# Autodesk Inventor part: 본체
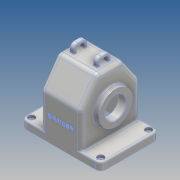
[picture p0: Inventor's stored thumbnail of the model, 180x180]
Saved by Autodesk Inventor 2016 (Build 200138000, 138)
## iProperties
Created: 2016-12
Part Number: 본체
Material: 알루미늄 6061
Document SubType Name: Modeling
Designer: Administrator
Density: 2.7 g/cm^3
Appearance: 알루미늄 - 평지
Mass: 1063.31 g
Surface Area: 1138.22 cm^2
Volume: 393.819 cm^3
Author: Administrator
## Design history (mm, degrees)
sketch "스케치1"
  geometry: L1 (-65, 55)-(65, 55); L2 (75, 45)-(75, -45); L3 (65, -55)-(-65, -55); L4 (-75, -45)-(-75, 45); L5 (-75, 55)-(75, -55); L6 (75, 55)-(-75, -55); A1 r 10 centre (-65, 45) between (-65, 55) and (-75, 45); A2 r 10 centre (-65, -45) between (-75, -45) and (-65, -55); A3 r 10 centre (65, -45) between (65, -55) and (75, -45); A4 r 10 centre (65, 45) between (75, 45) and (65, 55); 1 further point
  constraints: 12 end point, 8 point on circle, 8 point on line, 8 tangent, 4 centre point, 3 equal radius, 2 midpoint, 2 parallel, 1 horizontal, 1 perpendicular
  dimensions: "d0" = 150 distance of L5.end L6.end; "d1" = 110 distance of L6.start L5.end; "d2" = 10 radius of A1
extrude "돌출1" new body sketch "스케치1" distance "d3" = 15; taper "d4" = 0 deg
sketch "스케치2"
  geometry: L1 (-45, 15)-(-55, 15) reference; L2 (45, 15)-(-45, 15) reference; L3 (55, 15)-(45, 15) reference; L4 (-55, 15)-(-55, 76.847); L5 (-53.192, 82.583)-(-26.477, 120.736); L6 (-18.285, 125)-(18.285, 125); L7 (26.477, 120.736)-(53.192, 82.583); L8 (55, 76.847)-(55, 15); L9 (45, 0)-(-45, 0) reference; A1 r 10 centre (-18.285, 115) between (-18.285, 125) and (-26.477, 120.736); A2 r 10 centre (18.285, 115) between (26.477, 120.736) and (18.285, 125); A3 r 10 centre (45, 76.847) between (55, 76.847) and (53.192, 82.583); A4 r 10 centre (-45, 76.847) between (-53.192, 82.583) and (-55, 76.847); 3 further points
  constraints: 10 end point, 8 point on circle, 8 tangent, 4 centre point, 4 point on line, 3 equal radius, 2 vertical, 1 perpendicular
  dimensions: "d5" = 80 distance from line of point (55, 80) L9; "d6" = 80 distance from line of L9 point (-55, 80) (= d5); "d7" = 125 distance between parallel lines of L9 L6; "d8" = 35 deg angle of L5 L4; "d9" = 35 deg angle of L8 L7; "d10" = 10 radius of A1
extrude "돌출2" join sketch "스케치2" stored distance "d11" = 77; taper "d12" = 0 deg
sketch "스케치3"
  geometry: L1 (43.5, 65)-(-48.5, 65); L2 (-65, 0)-(65, 0) reference; L3 (38.5, 76.847)-(38.5, 15) reference; L4 (-38.5, 15)-(-38.5, 76.847) reference; L5 (43.5, 65)-(43.5, 102.5); L6 (43.5, 102.5)-(38.5, 102.5); L7 (38.5, 120.736)-(38.5, 82.583) reference; L8 (-38.5, 82.583)-(-38.5, 120.736) reference; L9 (-38.5, 96)-(-48.5, 96); L10 (-48.5, 96)-(-48.5, 65); L11 (-38.5, 96)-(38.5, 96); L12 (38.5, 102.5)-(38.5, 96); 1 further point
  constraints: 14 end point, 4 point on line, 3 perpendicular, 2 horizontal, 1 vertical
  dimensions: "d14" = 75 diameter of L6 L1; "d15" = 5 distance between parallel lines of L7 L5; "d17" = 65 distance between parallel lines of L2 L1; "d18" = 62 diameter of L9 L1; "d19" = 87 distance between parallel lines of L7 L10
revolve "회전1" sketch "스케치3" stored, may be unused: angle "d20" = 90 deg
sketch "스케치4"
  geometry: L1 (45, 0)-(-45, 0) reference; L2 (-53.192, 82.583)-(-26.477, 120.736) reference; L3 (-18.285, 125)-(18.285, 125) reference; L4 (26.477, 120.736)-(53.192, 82.583) reference; L5 (55, 76.847)-(55, 15) reference; L6 (-55, 15)-(-55, 76.847) reference; L7 (-55, 0)-(-55, 15) reference; L8 (55, 0)-(55, 15) reference; L9 (50, -5)-(50, 15); L10 (50, 15)-(50, 76.847); L11 (49.096, 79.715)-(22.381, 117.868); L12 (18.285, 120)-(-18.285, 120); L13 (-22.381, 117.868)-(-49.096, 79.715); L14 (-50, 76.847)-(-50, 15); L15 (-50, 15)-(-50, -5); L16 (-45, 0)-(-55, 0) reference; L17 (55, 0)-(45, 0) reference; L18 (-50, -5)-(50, -5); A1 r 10 centre (-18.285, 115) between (-18.285, 125) and (-26.477, 120.736) reference; A2 r 10 centre (18.285, 115) between (26.477, 120.736) and (18.285, 125) reference; A3 r 10 centre (45, 76.847) between (55, 76.847) and (53.192, 82.583) reference; A4 r 10 centre (-45, 76.847) between (-53.192, 82.583) and (-55, 76.847) reference; A5 r 5 centre (45, 76.847) between (50, 76.847) and (49.096, 79.715); A6 r 5 centre (18.285, 115) between (22.381, 117.868) and (18.285, 120); A7 r 5 centre (-18.285, 115) between (-18.285, 120) and (-22.381, 117.868); A8 r 5 centre (-45, 76.847) between (-49.096, 79.715) and (-50, 76.847); 1 further point
  constraints: 18 end point, 8 point on circle, 4 centre point, 2 collinear, 1 horizontal, 8 other
  dimensions: "d21" = 5 distance between parallel lines of L3 L12; "d22" = 5 distance between parallel lines of L1 L18
extrude "돌출3" cut sketch "스케치4" stored distance "d23" = 67; taper "d24" = 0 deg
fillet "모깎기1" dims "d25" = 8
fillet "모깎기2" dims "d26" = 3
sketch "스케치5"
  geometry: L1 (33.5, 106)-(19.5, 92); L2 (33.5, 65)-(-33.5, 65); L3 (-65, 0)-(65, 0) reference; L4 (33.5, 76.847)-(33.5, 0) reference; L5 (-33.5, 0)-(-33.5, 76.847) reference; L6 (43.5, 27.5)-(43.5, 102.5) reference; L7 (19.5, 65)-(19.5, 92); L8 (33.5, 116.147)-(33.5, 77.994) reference; L9 (33.5, 106)-(33.5, 65); 1 further point
  constraints: 9 end point, 4 point on line, 1 horizontal, 1 parallel
  dimensions: "d27" = 65 distance between parallel lines of L3 L2; "d28" = 24 distance between parallel lines of L6 L7; "d29" = 45 deg angle of L7 L1; "d30" = 27 distance of L7.start L1.end
revolve "회전2" sketch "스케치5" stored, may be unused: angle "d31" = 90 deg
sketch "스케치6"
  geometry: L1 (43.5, 27.5)-(43.5, 102.5) reference; L2 (43.5, 65)-(-48.5, 65); L3 (-48.5, 34)-(-48.5, 96) reference; L4 (43.5, 85)-(-48.5, 85); L5 (43.5, 85)-(43.5, 65); L6 (-48.5, 65)-(-48.5, 85); 1 further point
  constraints: 8 end point, 2 midpoint, 1 collinear, 1 parallel, 1 perpendicular
  dimensions: "d32" = 20 distance between parallel lines of L2 L4
revolve "회전3" sketch "스케치6" stored, may be unused: angle "d33" = 90 deg
fillet "모깎기3" dims "d34" = 3
sketch "스케치7"
  geometry: L1 (4.5, -5.785)-(12.5, -5.785); L2 (12.5, -5.785)-(12.5, -30.785); L3 (12.5, -30.785)-(4.5, -30.785); L4 (4.5, -30.785)-(4.5, -5.785); L5 (48.5, -5.785)-(56.5, -5.785); L6 (56.5, -5.785)-(56.5, -30.785); L7 (56.5, -30.785)-(48.5, -30.785); L8 (48.5, -30.785)-(48.5, -5.785); 2 further points
  constraints: 16 end point, 4 parallel, 2 horizontal, 2 perpendicular, 2 point on line, 1 horizontal alignment, 1 midpoint
  dimensions: "d35" = 25 distance of L3.end L1.start; "d36" = 8 distance of L1.start L1.end; "d37" = 8 distance of L5.start L5.end (= d36); "d38" = 18 distance from line of point (30.5, -18.285) L8; "d39" = 36 distance between parallel lines of L8 L2
extrude "돌출4" join sketch "스케치7" distance "d40" = 15; taper "d41" = 0 deg
sketch "스케치8"
  geometry: L1 (0, 25)-(0, 0) reference; L2 (-15, 0)-(-15, 25) reference; L3 (0, 0)-(-15, 0) reference; L4 (-10, 20)-(0, 20); L5 (0, 5)-(-10, 5); L6 (-10, 5)-(-10, 20); 1 further point
  constraints: 6 end point, 2 point on line, 1 other
  dimensions: "d42" = 5 distance between parallel lines of L2 L6; "d43" = 15 distance between parallel lines of L5 L4
extrude "돌출5" cut sketch "스케치8" stored distance "d44" = 15; taper "d45" = 0 deg
fillet "모깎기4" dims "d46" = 8
fillet "모깎기5" dims "d47" = 3
fillet "모깎기6" dims "d48" = 1
fillet "모깎기7" dims "d49" = 1
sketch "스케치9"
  geometry: A1 r 7 centre (65, -45) between (65, -52) and (72, -45) reference; A2 r 7 centre (65, 45) between (72, 45) and (65, 52) reference; A3 r 10 centre (-65, 45) between (-65, 55) and (-75, 45) reference; A4 r 10 centre (-65, -45) between (-75, -45) and (-65, -55) reference; 5 further points
  constraints: 4 coincident
hole "구멍1" sketch "스케치9" at (-65, 45), (-65, -45), (65, -45), (65, 45) diameter "d50" = 5; stored, may be unused: countersink angle "d54" = 90 deg, drill point angle "d56" = 0 deg; dims "d51" = 6, "d52" = 12, "d53" = 5, "d55" = 8
sketch "스케치10"
  geometry: C1 r 20 at (0, 0) reference; C2 r 31 at (0, 0) reference; A1 r 26 centre (0, 0) between (-26, 0) and (26, 0); 3 further points
  constraints: 4 point on circle, 2 horizontal alignment, 2 vertical alignment, 1 centre point, 1 coincident
  dimensions: "d57" = 52 diameter of A1
hole "구멍2" sketch "스케치10" at (-26, 0), (26, 0), (0, -26), (0, 26) diameter "d58" = 2.459; stored, may be unused: countersink angle "d62" = 90 deg, drill point angle "d64" = 118 deg; dims "d59" = 6, "d60" = 12, "d61" = 5, "d63" = 8
sketch "스케치11"
  geometry: C1 r 20 at (0, 0) reference; C2 r 37.5 at (0, 0) reference; A1 r 29 centre (0, 0) between (29, 0) and (0, 29); 3 further points
  constraints: 4 point on circle, 2 horizontal alignment, 2 vertical alignment, 1 centre point, 1 coincident
  dimensions: "d65" = 58 diameter of A1
hole "구멍3" sketch "스케치11" at (29, 0), (0, 29), (-29, 0), (0, -29) diameter "d66" = 2.459; stored, may be unused: countersink angle "d70" = 90 deg, drill point angle "d72" = 118 deg; dims "d67" = 6, "d68" = 12, "d69" = 5, "d71" = 8
chamfer "모따기1" distance "d73" = 1; stored, may be unused: second distance "d74" = 2, angle "d75" = 45 deg
sketch "스케치12"
  geometry: L1 (0, 0)-(130, 0) reference; C1 r 10 at (65, 45); 3 further points
  constraints: 1 centre point, 1 coincident, 1 midpoint, 1 vertical alignment, 1 other
  dimensions: "d76" = 20 diameter of C1; "d77" = 45 distance from line of C1.centre L1
feature "엠보싱1" sketch "스케치12" dims "d0" = 150, "d1" = 110, "d2" = 10, "d5" = 80, "d6" = 80 (= d5), "d7" = 125, "d8" = 35 deg, "d9" = 35 deg, "d10" = 10, "d78" = 0.5, "d79" = 0
node "솔리드1"
